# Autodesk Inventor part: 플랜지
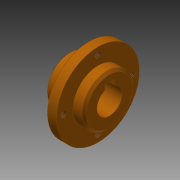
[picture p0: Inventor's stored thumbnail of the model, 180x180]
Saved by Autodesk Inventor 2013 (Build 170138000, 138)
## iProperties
Created: 2019-10
Part Number: 플랜지
Material: 스테인리스강
Document SubType Name: Modeling
Designer: mduedu
Density: 1 g/cm^3
Author: mduedu
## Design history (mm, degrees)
sketch "스케치1"
  geometry: L1 (0, 0)-(8, 0); L2 (8, 0)-(8, 10); L3 (8, 10)-(0, 10); L4 (0, 10)-(0, 0); L5 (8, 0)-(12, 0); L6 (12, 0)-(12, 18); L7 (12, 18)-(8, 18); L8 (8, 18)-(8, 0); L9 (12, 0)-(17, 0); L10 (17, 0)-(17, 11); L11 (17, 11)-(12, 11); L12 (12, 11)-(12, 0)
  constraints: 24 end point, 6 parallel, 3 horizontal, 3 perpendicular
  dimensions: "d0" = 17 distance between parallel lines of L10 L4; "d2" = 20 diameter of L3 L1; "d3" = 22 diameter of L11 L9; "d4" = 36 diameter of L7 L5; "d5" = 4 distance of L6.end L7.end; "d6" = 5 distance of L10.end L11.end
revolve "회전1" sketch "스케치1" stored, may be unused: angle "d7" = 90 deg
sketch "스케치2"
  geometry: L1 (-2, 5.123)-(2, 5.123); L2 (2, 5.123)-(2, 7.3); L3 (2, 7.3)-(-2, 7.3); L4 (-2, 7.3)-(-2, 5.123); A1 r 5.5 centre (0, 0) between (-2, 5.123) and (2, 5.123); 1 further point
  constraints: 8 end point, 2 parallel, 2 point on circle, 1 centre point, 1 coincident, 1 horizontal, 1 perpendicular
  dimensions: "d8" = 11 diameter of A1; "d10" = 4 distance of L2.end L3.end; "d11" = 7.3 distance from line of L3 point (0, 0)
extrude "돌출1" cut sketch "스케치2" stored distance "d12" = 10; taper "d13" = 0 deg
chamfer "모따기1" distance "d14" = 1; stored, may be unused: second distance "d15" = 2, angle "d16" = 45 deg
chamfer "모따기2" distance "d17" = 1; stored, may be unused: second distance "d18" = 2, angle "d19" = 45 deg
sketch "스케치3" dims "d20" = 30
  geometry: 3 further points
  constraints: 2 vertical alignment, 1 coincident, 2 other
hole "구멍1" sketch "스케치3" at (0, 15) diameter "d21" = 2.459; stored, may be unused: countersink angle "d25" = 90 deg, drill point angle "d27" = 118 deg; dims "d22" = 6, "d23" = 4, "d24" = 2, "d26" = 8
node "솔리드1"
pattern_circular "원형 패턴1" dims angle "d29" = 360 deg
